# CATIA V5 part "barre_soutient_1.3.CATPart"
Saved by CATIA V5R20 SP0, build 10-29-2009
Part number: barre_soutient_1.3
Bounding box of the stored display mesh (mm): x 460.778 to 500.778, y 316.602 to 1246.273, z -459.964 to -16.335
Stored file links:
  C:\Users\Mike-7\Desktop\MMS_GR3\bfoltzer\CFAO_bfoltzer\barre_soutient_1.3.CATPart
  D:\ecole\thinkmotion\Eolienne.CATProduct
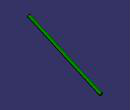
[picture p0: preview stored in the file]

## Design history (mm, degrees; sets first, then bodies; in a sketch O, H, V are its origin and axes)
Set1
  Plane1 "plan de bout de barre": linked copy from another document
  Point1: linked copy from another document
  Point2: linked copy from another document
  Plane2 "Plan de bout de barre": linked copy from another document
Body1 (main body)
  Sketch1 on Plane1, origin (0, 216.9152, -276.5365), H (-1, 0, 0), V (0, 0.4071, 0.9134)
    circle A1 centre (-480.7782, 264.8753) radius 20
    point P1 (-480.7782, 264.8753)
    reference projected point E1 (-480.7782, 264.8753) from Point1
    reference projected point E2 (-480.7782, 244.8753) from Point2
    coincidence: P1 E1, A1 E2
  Pad1: profile Sketch1, direction (0, 0.9134, -0.4071), up to Plane2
